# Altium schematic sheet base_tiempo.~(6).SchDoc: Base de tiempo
size A4; Revision: 1
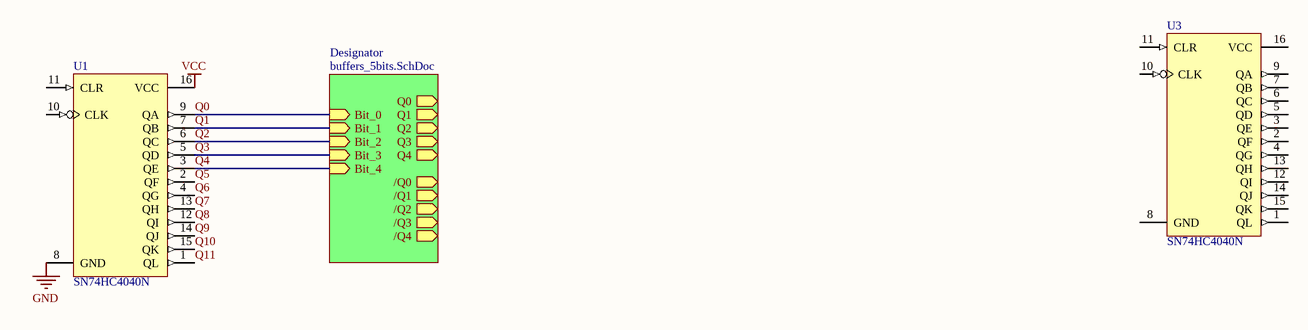
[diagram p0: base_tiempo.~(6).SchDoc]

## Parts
U1  SN74HC4040N  [N016]
U3  SN74HC4040N  [N016]

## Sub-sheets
Designator = buffers_5bits.SchDoc: Bit_0 (in), Bit_1 (in), Bit_2 (in), Bit_3 (in), Bit_4 (in), Q0 (out), Q1 (out), Q2 (out), Q3 (out), Q4 (out), /Q0 (out), /Q1 (out), /Q2 (out), /Q3 (out), /Q4 (out)

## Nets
GND: U1.8(GND)
VCC: U1.16(VCC)
Q0: U1.9(QA) ; sheet Designator/Bit_0
Q1: U1.7(QB) ; sheet Designator/Bit_1
Q2: U1.6(QC) ; sheet Designator/Bit_2
Q3: U1.5(QD) ; sheet Designator/Bit_3
Q4: U1.3(QE) ; sheet Designator/Bit_4
Q5: U1.2(QF)
Q6: U1.4(QG)
Q7: U1.13(QH)
Q8: U1.12(QI)
Q9: U1.14(QJ)
Q10: U1.15(QK)
Q11: U1.1(QL)

Not connected (* = marked no-connect by the designer): U1 10(CLK) 11(CLR); U3 1(QL) 2(QF) 3(QE) 4(QG) 5(QD) 6(QC) 7(QB) 8(GND) 9(QA) 10(CLK) 11(CLR) 12(QI) 13(QH) 14(QJ) 15(QK) 16(VCC)

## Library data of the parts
U1 U3 = SN74HC4040N: 12-Bit Asynchronous Binary Counter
